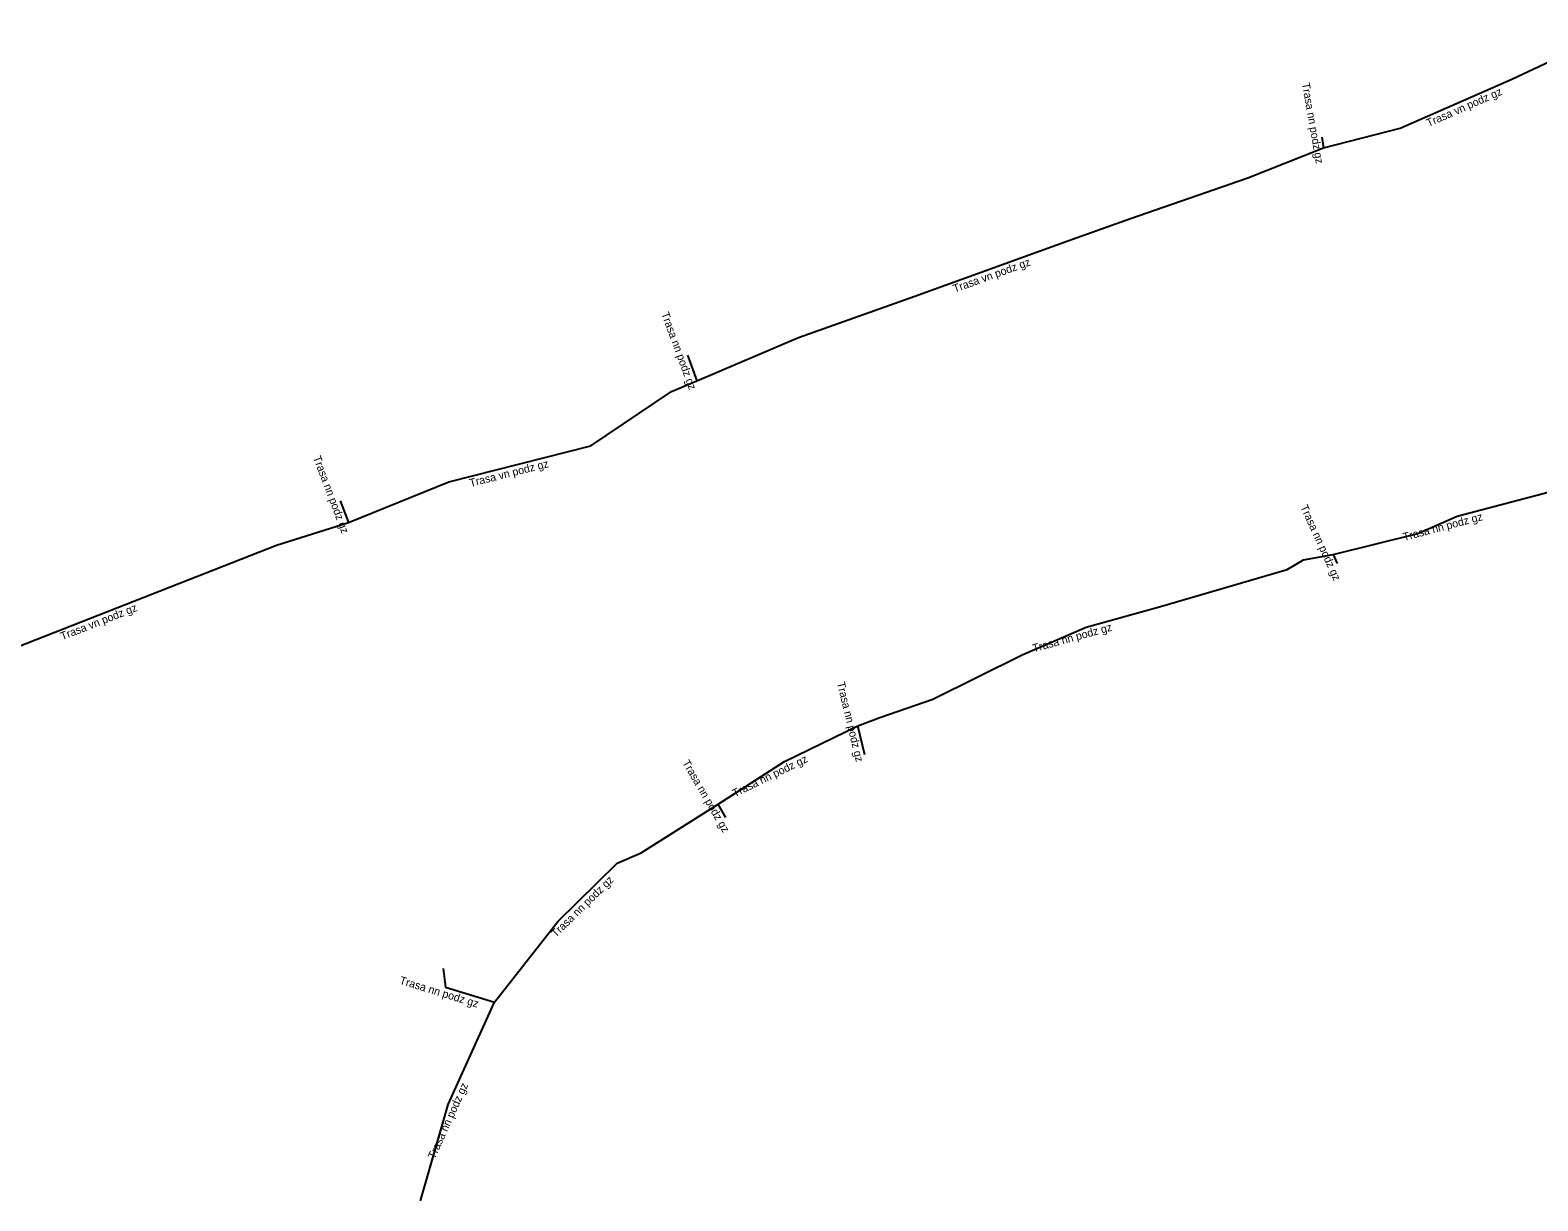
# Model space of a CAD drawing. Extents: x -688315 to -687940, y -1059595 to -1059240.
# Drawn here: x -688225 to -688130, y -1059511.5 to -1059437.7 of the extents above; entities that cross this region are included whole.
import ezdxf

# ---------------------------------------------------------------- set-up
doc = ezdxf.new("R2010")
doc.units = 0
for name, color, linetype in [('Popiskový text - Ostatní atributy Trasy', 7, 'Continuous'), ('Spojnice NN', 7, 'Continuous'), ('Spojnice VN', 7, 'Continuous')]:
    doc.layers.add(name, color=color, linetype=linetype)

msp = doc.modelspace()

# ---------------------------------------------------------------- linework, layer by layer
at = {"layer": 'Spojnice NN'}
for points in [[(-688143.59, -1059444.47), (-688143.47, -1059445.15)], [(-688183.58, -1059458.23), (-688182.99, -1059459.84)], [(-688142.88, -1059470.78), (-688137.54, -1059469.47), (-688135.05, -1059468.38), (-688126.61, -1059466.14)], [(-688205.46, -1059467.4), (-688204.94, -1059468.78)], [(-688172.83, -1059481.6), (-688171.45, -1059481.06), (-688168.11, -1059479.91), (-688162.48, -1059477.12), (-688158.45, -1059475.37), (-688153.76, -1059474.07), (-688145.77, -1059471.73), (-688144.75, -1059471.13), (-688142.88, -1059470.78)], [(-688142.88, -1059470.78), (-688142.62, -1059471.35)], [(-688181.64, -1059486.53), (-688177.45, -1059483.85), (-688172.83, -1059481.6)], [(-688172.39, -1059483.43), (-688172.83, -1059481.6)], [(-688195.75, -1059499.02), (-688191.75, -1059493.93), (-688188, -1059490.26), (-688186.49, -1059489.59), (-688181.64, -1059486.53)], [(-688181.15, -1059487.37), (-688181.64, -1059486.53)], [(-688198.98, -1059496.9), (-688198.83, -1059498.07), (-688195.75, -1059499.02)], [(-688200.41, -1059511.54), (-688198.65, -1059505.46), (-688195.75, -1059499.02)]]:
    msp.add_lwpolyline(points, dxfattribs=at)
at = {"layer": 'Spojnice VN'}
for points in [[(-688143.47, -1059445.15), (-688138.64, -1059443.91), (-688131.6, -1059440.82), (-688125.38, -1059437.89), (-688123.87, -1059437.73)], [(-688182.99, -1059459.84), (-688176.58, -1059457.1), (-688169.25, -1059454.5), (-688159.59, -1059451.02), (-688155.65, -1059449.61), (-688148.24, -1059447.05), (-688143.47, -1059445.15)], [(-688204.94, -1059468.78), (-688198.62, -1059466.21), (-688189.66, -1059463.94), (-688184.58, -1059460.51), (-688182.99, -1059459.84)], [(-688234.16, -1059479.86), (-688230.8, -1059478.56), (-688209.48, -1059470.21), (-688204.94, -1059468.78)]]:
    msp.add_lwpolyline(points, dxfattribs=at)

# ---------------------------------------------------------------- texts
at = {"layer": 'Popiskový text - Ostatní atributy Trasy'}
for s, rotation, p in [('Trasa nn podz gz', 280.00798, (-688144.847, -1059441.089)), ('Trasa vn podz gz', 23.69765, (-688136.864, -1059443.841)), ('Trasa vn podz gz', 19.81148, (-688166.73, -1059454.283)), ('Trasa nn podz gz', 290.12585, (-688185.235, -1059455.603)), ('Trasa nn podz gz', 290.64699, (-688207.181, -1059464.676)), ('Trasa vn podz gz', 14.21665, (-688197.254, -1059466.535)), ('Trasa nn podz gz', 294.51964, (-688144.957, -1059467.792)), ('Trasa nn podz gz', 14.86379, (-688138.397, -1059469.94)), ('Trasa vn podz gz', 21.38785, (-688222.989, -1059476.199)), ('Trasa nn podz gz', 15.4926, (-688161.745, -1059476.958)), ('Trasa nn podz gz', 283.51941, (-688174.152, -1059478.882)), ('Trasa nn podz gz', 25.96668, (-688180.592, -1059486.104)), ('Trasa nn podz gz', 300.25644, (-688183.919, -1059483.915)), ('Trasa nn podz gz', 44.38228, (-688191.877, -1059494.964)), ('Trasa nn podz gz', 342.85806, (-688201.765, -1059497.844)), ('Trasa nn podz gz', 65.75746, (-688199.506, -1059508.943))]:
    msp.add_text(s, height=0.5, rotation=rotation, dxfattribs=at).set_placement(p)

doc.saveas('drawing.dxf')
